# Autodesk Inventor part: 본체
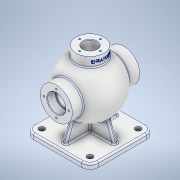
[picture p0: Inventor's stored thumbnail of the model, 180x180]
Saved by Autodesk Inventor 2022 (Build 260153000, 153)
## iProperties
Created: 2024-04
Part Number: 본체
Material: 알루미늄 6061
Document SubType Name: Modeling
Designer: Admin
Density: 2.7 g/cm^3
Appearance: 알루미늄 - 평지
Mass: 1526.72 g
Surface Area: 1173.82 cm^2
Volume: 565.453 cm^3
Author: Admin
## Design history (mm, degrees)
sketch "스케치1"
  geometry: L1 (0, 92.864)-(0, -99.249); A1 r 54 centre (0, 0) between (0, -54) and (0, 54); 1 further point
  constraints: 3 point on line, 2 end point, 2 point on circle, 1 centre point, 1 coincident, 1 vertical
  dimensions: "d0" = 108 diameter of A1
revolve "회전1" sketch "스케치1" stored, may be unused: angle "d1" = 90 deg
node "작업 평면1"
sketch "스케치3"
  geometry: L1 (-62.5, 62.5)-(62.5, 62.5); L2 (62.5, 62.5)-(62.5, -62.5); L3 (62.5, -62.5)-(-62.5, -62.5); L4 (-62.5, -62.5)-(-62.5, 62.5); L5 (-62.5, 62.5)-(62.5, -62.5); L6 (62.5, 62.5)-(-62.5, -62.5); 1 further point
  constraints: 12 end point, 2 midpoint, 2 parallel, 1 horizontal, 1 perpendicular
  dimensions: "d3" = 125 distance of L2.end L3.end; "d4" = 125 distance of L1.end L2.end
extrude "돌출1" join sketch "스케치3" distance "d5" = 10; taper "d6" = 0 deg
sketch "스케치4"
  geometry: L1 (-75, -62.5)-(-75, 62.5) reference; L2 (-75, 50.5)-(0, 23.202); L3 (0, 23.202)-(0, -23.202); L4 (0, -23.202)-(-75, -50.5); L5 (-75, 50.5)-(-75, -50.5); L6 (-85, 62.5)-(-75, 62.5) reference; L7 (-112.8, 0)-(81.8, 0) reference; 1 further point
  constraints: 8 end point, 2 parallel, 2 point on line, 2 symmetric about line, 1 midpoint
  dimensions: "d7" = 12 distance from line of L6 L2.start; "d8" = 20 deg angle of L2 L6
extrude "돌출2" join sketch "스케치4" stored distance "d9" = 8; taper "d10" = 0 deg
sketch "스케치5"
  geometry: L1 (-62.5, -75)-(62.5, -75) reference; L2 (50.5, -75)-(23.202, 0); L3 (23.202, 0)-(-23.202, 0); L4 (-23.202, 0)-(-50.5, -75); L5 (50.5, -75)-(-50.5, -75); L6 (62.5, -85)-(62.5, -75) reference; L7 (0, -112.8)-(0, 81.8) reference; 1 further point
  constraints: 8 end point, 2 horizontal, 2 point on line, 2 symmetric about line, 1 midpoint
  dimensions: "d11" = 12 distance of L1.end L2.start; "d12" = 20 deg angle of L6 L2
extrude "돌출3" join sketch "스케치5" stored distance "d13" = 8; taper "d14" = 0 deg
node "작업 평면2"
sketch "스케치6"
  geometry: C1 r 27 at (0, 0); 1 further point
  constraints: 1 centre point, 1 coincident
  dimensions: "d16" = 54 diameter of C1
extrude "돌출4" join sketch "스케치6" stored distance "d17" = 8; taper "d18" = 0 deg
node "작업 평면3"
sketch "스케치7"
  geometry: C1 r 31 at (0, 0); 1 further point
  constraints: 1 centre point, 1 coincident
  dimensions: "d20" = 62 diameter of C1
extrude "돌출5" join sketch "스케치7" distance "d21" = 130; taper "d22" = 0 deg
sketch "스케치8"
  geometry: L1 (0, 137.901)-(0, -191.245); L2 (-115, 0)-(95, 0) reference; L3 (31, 65)-(-31, 65) reference; L4 (0, 65)-(17.5, 65); L5 (17.5, 65)-(17.5, 49); L6 (17.5, 49)-(0, 49); L7 (0, 49)-(0, 65); L8 (0, 49)-(15, 49); L9 (15, 49)-(15, 41.364); L10 (15, 41.364)-(0, 41.364); L11 (0, 41.364)-(0, 49); L12 (31, -65)-(-31, -65) reference; L13 (0, -65)-(17.5, -65); L14 (17.5, -65)-(17.5, -49); L15 (17.5, -49)-(0, -49); L16 (0, -49)-(0, -65); L17 (0, -49)-(15, -49); L18 (15, -49)-(15, -41.364); L19 (15, -41.364)-(0, -41.364); L20 (0, -41.364)-(0, -49); A1 r 44 centre (0, 0) between (15, -41.364) and (15, 41.364); 7 further points
  constraints: 34 end point, 8 parallel, 4 horizontal, 4 perpendicular, 3 point on line, 2 midpoint, 2 point on circle, 1 centre point, 1 coincident, 1 vertical
  dimensions: "d23" = 44 radius of A1; "d24" = 16 distance of L4.end L5.end; "d25" = 16 distance of L13.end L14.end; "d26" = 35 diameter of L5 L1; "d27" = 30 diameter of L9 L1
revolve "회전2" sketch "스케치8" stored, may be unused: angle "d28" = 90 deg
sketch "스케치9"
  geometry: C1 r 13 at (0, 0); C2 r 27 at (0, 0) reference; 1 further point
  constraints: 1 centre point, 1 concentric
  dimensions: "d29" = 26 diameter of C1
extrude "돌출6" cut sketch "스케치9" stored distance "d30" = 130; taper "d31" = 0 deg
sketch "스케치10" dims "d32" = 48
  geometry: L1 (-87.5, 0)-(87.5, 0) reference; L2 (0, -115)-(0, 95) reference; C1 r 31 at (0, 0) reference; 3 further points
  constraints: 1 point on line, 1 vertical alignment, 3 other
hole "구멍1" sketch "스케치10" at (0, 24) diameter "d33" = 3.242; stored, may be unused: countersink angle "d37" = 90 deg, drill point angle "d39" = 118 deg; dims "d34" = 12, "d35" = 4, "d36" = 2, "d38" = 15
sketch "스케치11" dims "d43" = 40
  geometry: L1 (0, 91)-(0, -91) reference; C1 r 27 at (0, 0) reference; 3 further points
  constraints: 1 point on line, 1 vertical alignment, 3 other
hole "구멍2" sketch "스케치11" at (0, -20) diameter "d44" = 3.242; stored, may be unused: countersink angle "d48" = 90 deg, drill point angle "d50" = 118 deg; dims "d45" = 9, "d46" = 4, "d47" = 2, "d49" = 11
node "작업 평면4"
sketch "스케치12"
  geometry: L1 (-115, 0)-(95, 0) reference; L2 (65, 27)-(65, -27) reference; 2 further points
  constraints: 1 point on line, 1 other
  dimensions: "d55" = 9 distance from line of L2 point (56, 0)
feature "엠보싱1" sketch "스케치12" dims "d56" = 0.5, "d57" = 0
fillet "모깎기1" dims "d58" = 0.6
fillet "모깎기2" dims "d59" = 0.6
chamfer "모따기1" distance "d60" = 1; stored, may be unused: second distance "d61" = 2, angle "d62" = 45 deg
chamfer "모따기2" distance "d63" = 1; stored, may be unused: second distance "d64" = 2, angle "d65" = 45 deg
fillet "모깎기3" dims "d66" = 3
fillet "모깎기4" dims "d67" = 3
fillet "모깎기5" dims "d68" = 3
fillet "모깎기6" dims "d69" = 16
sketch "스케치13"
  geometry: L1 (-62.5, 46.5)-(-62.5, -46.5) reference; L2 (-46.5, -62.5)-(46.5, -62.5) reference; L3 (62.5, -46.5)-(62.5, 46.5) reference; L4 (46.5, 62.5)-(-46.5, 62.5) reference; L5 (-1, -52.601)-(1, -52.601) reference; L6 (-7, -7)-(-7, -46.216) reference; L7 (-46.216, -7)-(-7, -7) reference; L8 (-52.601, 1)-(-52.601, -1) reference; L9 (-7, 7)-(-46.216, 7) reference; L10 (-7, 46.216)-(-7, 7) reference; L11 (1, 52.601)-(-1, 52.601) reference; L12 (7, 7)-(7, 46.216) reference; L13 (46.216, 7)-(7, 7) reference; L14 (52.601, -1)-(52.601, 1) reference; L15 (7, -7)-(46.216, -7) reference; L16 (7, -46.216)-(7, -7) reference; C1 r 5.5 at (-46.5, -46.5); C2 r 5.5 at (46.5, -46.5); C3 r 5.5 at (-46.5, 46.5); C4 r 5.5 at (46.5, 46.5); A1 r 16 centre (-46.5, 46.5) between (-46.5, 62.5) and (-62.5, 46.5) reference; A2 r 16 centre (-46.5, -46.5) between (-62.5, -46.5) and (-46.5, -62.5) reference; A3 r 16 centre (46.5, -46.5) between (46.5, -62.5) and (62.5, -46.5) reference; A4 r 16 centre (46.5, 46.5) between (62.5, 46.5) and (46.5, 62.5) reference; A5 r 16 centre (-46.5, 46.5) between (-46.5, 62.5) and (-62.5, 46.5) reference; A6 r 16 centre (-46.5, -46.5) between (-62.5, -46.5) and (-46.5, -62.5) reference; 9 further points; 8 other entities
  constraints: 4 centre point, 4 concentric, 8 other
  dimensions: "d70" = 11 diameter of C1; "d71" = 11 diameter of C2; "d72" = 11 diameter of C3; "d73" = 11 diameter of C4
extrude "돌출7" cut sketch "스케치13" extent not by distance; stored distance "d74" = 0; taper "d75" = 0 deg
fillet "모깎기7" dims "d76" = 3
chamfer "모따기3" distance "d77" = 1; stored, may be unused: second distance "d78" = 2, angle "d79" = 45 deg
node "솔리드1"
pattern_circular "원형 패턴1" dims angle "d41" = 360 deg
mirror "미러1"
pattern_circular "원형 패턴2" dims angle "d52" = 360 deg
node "투영된 루프1"
feature "A9D066F2-1C7D-4E18-AEED-F7BC21143FA4" dims "d33" = 3.242, "d34" = 12, "d35" = 4, "d36" = 2, "d37" = 90 deg, "d38" = 15, "d39" = 118 deg
other parameters: "d2" = -85, "d19" = -65, "d54" = 243
